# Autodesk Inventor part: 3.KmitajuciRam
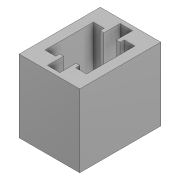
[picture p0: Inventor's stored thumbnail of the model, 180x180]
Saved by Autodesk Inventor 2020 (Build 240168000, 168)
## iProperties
Created: 2022-02
Part Number: 3.KmitajuciRam
Material: Prusa ASA
Document SubType Name: Modeling
Designer: marti
Density: 0.321 g/cm^3
Appearance: Smooth - White(2)
Mass: 10.7071 g
Surface Area: 132.421 cm^2
Volume: 33.3553 cm^3
Author: marti
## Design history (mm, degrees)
sketch "Sketch1"
  geometry: L1 (15, 20.1)-(-15, 20.1); L2 (-15, 20.1)-(-15, -20.1); L3 (-15, -20.1)-(15, -20.1); L4 (15, -20.1)-(15, 20.1); L5 (15, 20.1)-(-15, -20.1); L6 (-15, 20.1)-(15, -20.1); 1 further point
  constraints: 12 end point, 2 midpoint, 2 parallel, 1 horizontal, 1 perpendicular
  dimensions: "d0" = 30 distance of L3.end L2.end; "d1" = 40.2 distance of L2.end L1.end
extrude "Extrusion1" new body sketch "Sketch1" distance "d2" = 36; taper "d3" = 0 deg
sketch "Sketch2"
  geometry: L1 (10.275, 12)-(4.975, 12); L2 (4.975, 12)-(4.975, -12); L3 (4.975, -12)-(10.275, -12); L4 (10.275, -12)-(10.275, 12); L5 (15, 20.1)-(-15, 20.1) reference; L6 (-4.975, 12)-(-10.275, 12); L7 (-10.275, 12)-(-10.275, -12); L8 (-10.275, -12)-(-4.975, -12); L9 (-4.975, -12)-(-4.975, 12); L10 (3.075, 15)-(-3.075, 15); L11 (-3.075, 15)-(-3.075, -15); L12 (-3.075, -15)-(3.075, -15); L13 (3.075, -15)-(3.075, 15); L14 (3.075, 15)-(-3.075, -15); L15 (-3.075, 15)-(3.075, -15); L16 (4.975, 10)-(2.975, 10); L17 (2.975, 10)-(2.975, -10); L18 (2.975, -10)-(4.975, -10); L19 (4.975, -10)-(4.975, 10); L20 (-4.975, 10)-(-3.075, 10); L21 (-3.075, 10)-(-3.075, -10); L22 (-3.075, -10)-(-4.975, -10); L23 (-4.975, -10)-(-4.975, 10); 6 further points
  constraints: 44 end point, 10 parallel, 5 horizontal, 5 perpendicular, 5 point on line, 2 midpoint
  dimensions: "d4" = 5.3 distance of L3.end L2.end; "d5" = 24 distance of L2.end L1.end; "d6" = 8.1 distance between parallel lines of L5 L1; "d7" = 5.3 distance of L8.end L7.end; "d8" = 24 distance of L7.end L6.end; "d9" = 8.1 distance between parallel lines of L5 L6; "d10" = 6.15 distance of L12.end L11.end; "d11" = 30 distance of L11.end L10.end; "d12" = 1.9 distance between parallel lines of L13 L2; "d13" = 1.9 distance between parallel lines of L9 L11; "d14" = 2 distance of L18.end L17.end; "d15" = 20 distance of L17.end L16.end
extrude "Extrusion2" cut sketch "Sketch2" distance "d16" = 30; taper "d17" = 0 deg
sketch "Sketch3"
  geometry: L1 (3.075, 18)-(-3.075, 18); L2 (-3.075, 18)-(-3.075, -18); L3 (-3.075, -18)-(3.075, -18); L4 (3.075, -18)-(3.075, 18); L5 (3.075, 18)-(-3.075, -18); L6 (-3.075, 18)-(3.075, -18); 1 further point
  constraints: 12 end point, 2 midpoint, 2 parallel, 1 horizontal, 1 perpendicular
  dimensions: "d18" = 6.15 distance of L3.end L2.end; "d19" = 36 distance of L2.end L1.end
extrude "Extrusion3" cut sketch "Sketch3" distance "d20" = 36; taper "d21" = 0 deg
sketch "Sketch14" dims "d107" = 10
  geometry: L1 (3.075, -18)-(3.075, 18) reference; L2 (4.975, 10)-(3.075, 10) reference; L3 (3.075, 10)-(4.975, 10); L4 (10.275, 12)-(4.975, 12) reference; L5 (4.975, 10)-(4.975, 12); L6 (10.275, -12)-(10.275, 12) reference; L7 (4.975, 12)-(10.275, 12); L8 (4.975, -12)-(10.275, -12) reference; L9 (10.275, 12)-(10.275, -12); L10 (10.275, -12)-(4.975, -12); L11 (-15, 20.1)-(15, 20.1) reference; L12 (15, 20.1)-(15, -20.1) reference; L13 (15, -20.1)-(-15, -20.1) reference; C1 r 2 at (10, 16.1); C2 r 2 at (10, -16.1); C3 r 2 at (-10, 16.1); C4 r 2 at (-10, -16.1); 1 further point
  constraints: 10 end point, 4 centre point, 3 perpendicular, 2 horizontal, 1 collinear, 4 other
  dimensions: "d96" = 4 diameter of C1; "d98" = 4 distance from line of L11 C1.centre; "d101" = 4 distance from line of C2.centre L13; "d104" = 20 distance of C1.centre C3.centre; "d120" = 5 distance from line of L12 C1.centre; "d121" = 5 distance from line of L12 C2.centre
extrude "Extrusion12" cut sketch "Sketch14" distance "d109" = 14; taper "d110" = 0 deg
fillet "Fillet3" dims "d117" = 2
body "Solid1"
